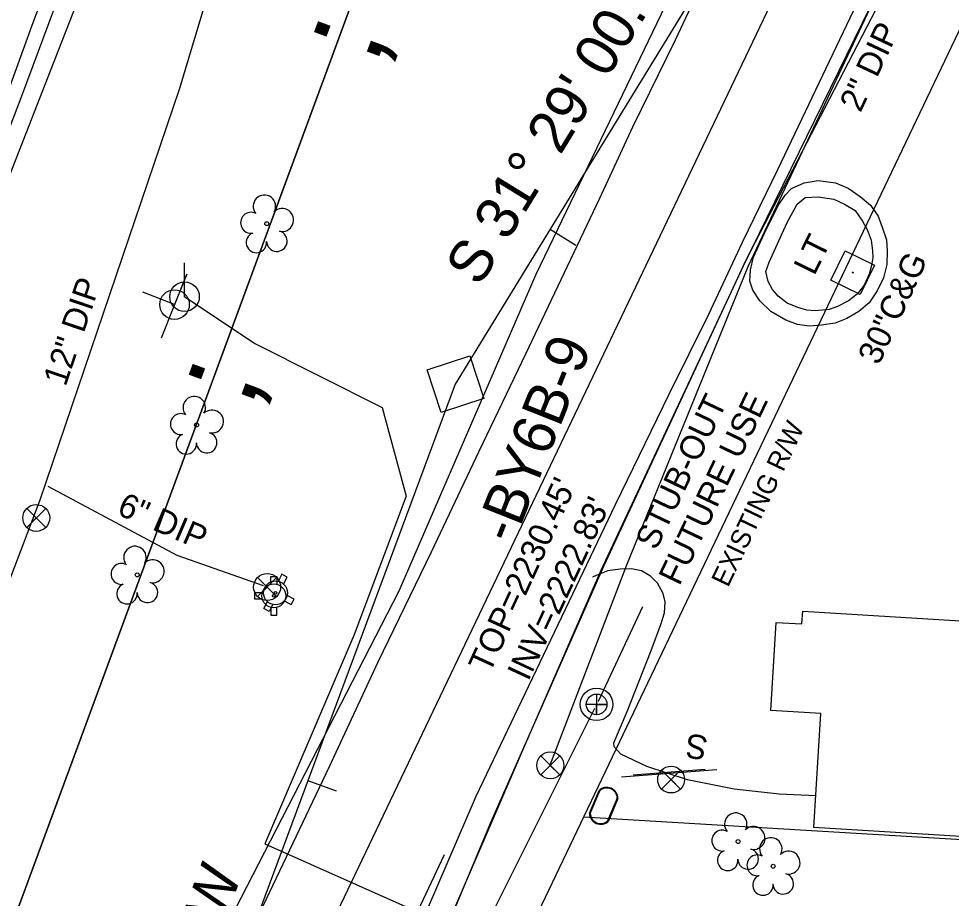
# Model space of a CAD drawing. Extents: x 945964 to 948456, y 631061 to 636061.
# Drawn here: x 947403.5 to 947557.8, y 634522.6 to 634668.2 of the extents above; entities that cross this region are included whole.
import ezdxf

# ---------------------------------------------------------------- set-up
doc = ezdxf.new("R2010")
doc.units = 0
for name, color, linetype in [('CTL Supplemental Horizontal and Vertical CELL', 7, 'Continuous'), ('Exist Building', 7, 'Continuous'), ('Exist Horizontal Alignment', 7, 'Continuous'), ('Exist Horizontal Baseline Alignment', 7, 'Continuous'), ('Exist Horizontal Baseline Alignment Direction Label', 7, 'Continuous'), ('Exist Horizontal Baseline Alignment Station Label', 7, 'Continuous'), ('Exist Horizontal Baseline Alignment Tick small', 7, 'Continuous'), ('Exist Other Culture Fence Line', 7, 'Continuous'), ('Exist Other Culture Sign CELL', 7, 'Continuous'), ('Exist Other Culture Sign Text', 7, 'Continuous'), ('Exist Property Line', 7, 'Continuous'), ('Exist Right of Way Control of Access CA Symbol CELL', 7, 'Continuous'), ('Exist Right of Way Control of Access Line', 7, 'Continuous'), ('Exist Right of Way Line', 7, 'Continuous'), ('Exist Right of Way Line Text', 7, 'Continuous'), ('Exist Roads Curbs', 7, 'Continuous'), ('Exist Roads Curbs Text', 7, 'Continuous'), ('Exist Roads EOP', 7, 'Continuous'), ('Exist Roads EOP Other', 7, 'Continuous'), ('Exist Utilities Gas UG Line SUE', 7, 'Continuous'), ('Exist Utilities Other Pole With Base CELL', 7, 'Continuous'), ('Exist Utilities Other Pole With Base Text', 7, 'Continuous'), ('Exist Utilities Power Joint Use Telephone CELL', 7, 'Continuous'), ('Exist Utilities Power Pole CELL', 7, 'Continuous'), ('Exist Utilities Sanitary Sewer Manhole CELL', 7, 'Continuous'), ('Exist Utilities Sanitary Sewer Manhole Text', 7, 'Continuous'), ('Exist Utilities Sanitary Sewer UG Line', 7, 'Continuous'), ('Exist Utilities Sanitary Sewer UG Line Invert Elevation', 7, 'Continuous'), ('Exist Utilities Telephone UG Cable SUE', 7, 'Continuous'), ('Exist Utilities Telephone UG FO SUE', 7, 'Continuous'), ('Exist Utilities TV UG Cable SUE', 7, 'Continuous'), ('Exist Utilities Water Fire Hydrant CELL', 7, 'Continuous'), ('Exist Utilities Water Meter CELL', 7, 'Continuous'), ('Exist Utilities Water UG Line SUE', 7, 'Continuous'), ('Exist Utilities Water UG Line SUE Text', 7, 'Continuous'), ('Exist Utilities Water Valve CELL', 7, 'Continuous'), ('Exist Vegetation Tree CELL', 7, 'Continuous')]:
    doc.layers.add(name, color=color, linetype=linetype)

# ---------------------------------------------------------------- blocks, each defined once
blk = doc.blocks.new('EXIST UTILITIES WATER FIRE HYDRANT')
at = {"layer": 'Exist Utilities Water Fire Hydrant CELL'}
blk.add_line((0, 0), (0, 0), dxfattribs=at)
for points in [[(-0.0103, 0.0382), (-0.0103, 0.064), (0.0103, 0.064), (0.0103, 0.0377)], [(-0.0382, 0.0103), (-0.064, 0.0103), (-0.064, -0.0103), (-0.0382, -0.0103)], [(-0.0103, -0.0382), (-0.0103, -0.064), (0.0103, -0.064), (0.0103, -0.0377)]]:
    blk.add_lwpolyline(points, dxfattribs=at)
for radius in [0.0395, 0.00485]:
    blk.add_circle((0, 0), radius, dxfattribs=at)
blk = doc.blocks.new('EXIST UTILITIES POWER JOINT USE TELEPHONE')
at = {"layer": 'Exist Utilities Power Joint Use Telephone CELL'}
blk.add_line((0, 0), (0, 0), dxfattribs=at)
blk.add_lwpolyline([(-0.1188, 0), (0.108, -0.0008), (0, -0.0004), (0, 0.1125)], dxfattribs=at)
blk.add_circle((0, 0.0001), 0.049, dxfattribs=at)
blk = doc.blocks.new('CTL SUPPLEMENTAL HORIZONTAL AND VERTICAL')
at = {"layer": 'CTL Supplemental Horizontal and Vertical CELL'}
blk.add_line((0, 0), (0, 0), dxfattribs=at)
blk.add_lwpolyline([(-0.0735, 0.074), (0.07475, 0.074), (0.07475, -0.0745), (-0.0735, -0.0745)], close=True, dxfattribs=at)
blk = doc.blocks.new('EXIST UTILITIES WATER METER')
at = {"layer": 'Exist Utilities Water Meter CELL'}
blk.add_line((0, 0), (0, 0), dxfattribs=at)
for points in [[(-0.0408, 0.034), (0.0408, 0.034)], [(-0.0408, 0.0312), (0.0408, 0.0312)], [(0.0408, -0.0312), (-0.0413, -0.0312)], [(0.0408, -0.034), (-0.0413, -0.034)]]:
    blk.add_lwpolyline(points, dxfattribs=at)
for centre, radius, start, end in [((-0.0261, -0.0001), 0.0371, 113.178, 245.9794), ((-0.0259, -0.0001), 0.0347, 115.3009, 243.7824), ((0.0259, 0), 0.0371, 293.6483, 66.3084), ((0.0261, 0), 0.0345, 295.1272, 64.8728)]:
    blk.add_arc(centre, radius, start, end, dxfattribs=at)
blk = doc.blocks.new('EXIST UTILITIES WATER VALVE')
at = {"layer": 'Exist Utilities Water Valve CELL'}
blk.add_lwpolyline([(0.0315, 0.0315), (-0.0315, -0.0315), (0, 0), (0.0315, -0.0315), (-0.0315, 0.0315)], dxfattribs=at)
blk.add_circle((0, 0), 0.0445, dxfattribs=at)

msp = doc.modelspace()

# ---------------------------------------------------------------- linework, layer by layer
at = {"layer": 'Exist Building'}
msp.add_lwpolyline([(947533.24, 634570.16), (947642.08, 634563.46), (947645.55, 634619.91), (947640.35, 634620.23), (947641.33, 634636.15), (947646.37, 634635.84), (947646.93, 634644.89), (947682.78, 634642.68), (947675.59, 634525.72), (947535.1, 634534.36), (947536.26, 634553.22), (947527.95, 634553.73), (947528.84, 634568.29), (947533.11, 634568.02)], close=True, dxfattribs=at)
at = {"layer": 'Exist Horizontal Alignment'}
msp.add_line((947634.91, 634894.66), (947405.56, 634414.27), dxfattribs=at)
at = {"layer": 'Exist Horizontal Baseline Alignment'}
for p, q in [((947700.35, 634974.44), (947475.75, 634607.69)), ((947475.75, 634607.69), (947365.74, 634311.71))]:
    msp.add_line(p, q, dxfattribs=at)
at = {"layer": 'Exist Horizontal Baseline Alignment Tick small'}
for p, q in [((947491.45, 634633.33), (947495.71, 634630.72)), ((947451.38, 634542.13), (947456.07, 634540.39))]:
    msp.add_line(p, q, dxfattribs=at)
at = {"layer": 'Exist Other Culture Fence Line'}
msp.add_lwpolyline([(947583.12, 635010.41), (947482.79, 634736.39), (947398.27, 634507.1), (947363.07, 634405.71)], dxfattribs=at)
at = {"layer": 'Exist Other Culture Sign CELL'}
for p, q in [((947519.04, 634543.87), (947503.27, 634542.67)), ((947505.17, 634543.08), (947517.12, 634544.02))]:
    msp.add_line(p, q, dxfattribs=at)
at = {"layer": 'Exist Property Line'}
msp.add_lwpolyline([(947694.12, 634524.25), (947693.06, 634524.31), (947496.95, 634536.07)], dxfattribs=at)
at = {"layer": 'Exist Right of Way Control of Access CA Symbol CELL'}
msp.add_line((947437.37, 634613.19), (947437.37, 634613.19), dxfattribs=at)
at = {"layer": 'Exist Right of Way Control of Access Line'}
msp.add_lwpolyline([(947398.27, 634507.1), (947482.79, 634736.39)], dxfattribs=at)
at = {"layer": 'Exist Right of Way Line'}
msp.add_line((947661.98, 634881.73), (947432.63, 634401.34), dxfattribs=at)
at = {"layer": 'Exist Roads Curbs'}
for points in [[(947414.14, 634682.65), (947403.95, 634655.19), (947386.91, 634610.72)], [(947544.59, 634631.52), (947544.76, 634629.77), (947544.84, 634628.67), (947544.61, 634627.36), (947544.23, 634625.89), (947543.4, 634624.1), (947542.26, 634622.62), (947540.82, 634621.49), (947538.97, 634620.54), (947537.59, 634620.05), (947535.29, 634619.82), (947533.9, 634619.97), (947532.45, 634620.38), (947530.64, 634621.13), (947529.19, 634622.27), (947528.24, 634623.36), (947527.5, 634624.68), (947527.16, 634626.34), (947527.68, 634627.89), (947530.69, 634634.44), (947532.32, 634637.52), (947533.65, 634638.58), (947535.82, 634638.68), (947538.39, 634638.33), (947540.15, 634637.49), (947541.91, 634636.43), (947543.14, 634634.66), (947543.91, 634633.29), (947544.59, 634631.52)]]:
    msp.add_lwpolyline(points, dxfattribs=at)
at = {"layer": 'Exist Roads EOP'}
for points in [[(947416.94, 634696.72), (947405.89, 634667.48), (947397.84, 634645.46)], [(947398.51, 634422.19), (947405.3, 634438.3), (947412.75, 634454.81), (947421.56, 634473.6), (947428.38, 634488.03), (947437.98, 634508.75), (947454.98, 634544.45), (947463.03, 634561.75), (947471.85, 634579.95), (947479.72, 634596.64), (947487.41, 634612.7), (947499.7, 634638.47), (947505.16, 634650.3), (947512.22, 634664.7), (947520.77, 634683.05)], [(947469.78, 634517.62), (947479.2, 634539.5), (947486.18, 634554.11), (947494.6, 634571.73), (947502.28, 634587.82), (947502.28, 634587.82), (947511.16, 634606.03), (947511.16, 634606.03), (947517.72, 634619.27), (947517.72, 634619.27), (947523.3, 634631.23), (947529.13, 634643.22), (947542.23, 634670.73)], [(947409.98, 634383.21), (947412.91, 634391.97), (947419.73, 634410.82), (947424.3, 634422.36), (947430.21, 634435.76), (947435.78, 634448.39), (947442.34, 634461.96), (947446.32, 634471.45), (947464.44, 634509.58), (947473.96, 634529.87)]]:
    msp.add_lwpolyline(points, dxfattribs=at)
at = {"layer": 'Exist Roads EOP Other'}
for points in [[(947527.21, 634633.28), (947529.29, 634637.44), (947530.32, 634639.01), (947531.4, 634640.11), (947533.47, 634641.05), (947535.81, 634641.39), (947538.65, 634641.04), (947540.77, 634640.16), (947542.75, 634638.78), (947544.48, 634637.34), (947545.73, 634635.49), (947546.38, 634633.71), (947547.1, 634631.6), (947547.23, 634629.73), (947547.15, 634627.5), (947546.58, 634625.33), (947545.53, 634623.16), (947544.21, 634621.18), (947542.52, 634619.71), (947540.52, 634618.56), (947538.61, 634617.79), (947536.35, 634617.46), (947534.29, 634617.33), (947532.4, 634617.6), (947530.43, 634618.27), (947527.97, 634619.73), (947526.13, 634621.51), (947525, 634623.26), (947524.51, 634624.75), (947524.6, 634626.63), (947525.09, 634628.71), (947527.21, 634633.28)], [(947535.42, 634539.57), (947529.33, 634539.85), (947521.92, 634540.69), (947514.17, 634542.23), (947507.43, 634544.45), (947503.13, 634546.5), (947502.07, 634547.67), (947502.01, 634548.33), (947504.22, 634553.54), (947508.15, 634563.64), (947509.77, 634567.94), (947510.39, 634569.89), (947510.5, 634571.67), (947510.14, 634573.07), (947509.22, 634574.8), (947508.04, 634575.92), (947506.59, 634576.79), (947504.91, 634577.16), (947503.03, 634577.11), (947501, 634576.82), (947499.08, 634576.03), (947498.46, 634575.78)]]:
    msp.add_lwpolyline(points, dxfattribs=at)
at = {"layer": 'Exist Utilities Gas UG Line SUE'}
msp.add_lwpolyline([(947411.39, 634357.39), (947432.81, 634416.73), (947448.6, 634452.89), (947466.55, 634499.81), (947487.41, 634548.32), (947499.89, 634576.91), (947523.42, 634627.31), (947572, 634726.59), (947594.13, 634772.03), (947617.16, 634817.01), (947638.9, 634858.44), (947663.24, 634905.68), (947679.1, 634930.67), (947690.74, 634971.53), (947694.38, 634980.36)], dxfattribs=at)
at = {"layer": 'Exist Utilities Other Pole With Base CELL'}
msp.add_line((947541.51, 634626.19), (947541.51, 634626.19), dxfattribs=at)
msp.add_lwpolyline([(947537.89, 634624.91), (947540.24, 634629.77), (947545.1, 634627.42), (947542.75, 634622.56), (947537.89, 634624.91)], dxfattribs=at)
msp.add_circle((947541.51, 634626.19), 0.0707, dxfattribs=at)
at = {"layer": 'Exist Utilities Power Pole CELL'}
for q in [(947430.97, 634627.8), (947430.97, 634622.18)]:
    msp.add_line((947430.97, 634622.18), q, dxfattribs=at)
msp.add_circle((947430.97, 634622.18), 2.45, dxfattribs=at)
at = {"layer": 'Exist Utilities Sanitary Sewer Manhole CELL'}
msp.add_lwpolyline([(947499.14, 634556.43), (947499.14, 634553.01), (947499.14, 634554.72), (947500.86, 634554.72), (947497.43, 634554.72)], dxfattribs=at)
for radius in [2.69, 1.71]:
    msp.add_circle((947499.14, 634554.72), radius, dxfattribs=at)
at = {"layer": 'Exist Utilities Sanitary Sewer UG Line'}
for p, q in [((947499.45, 634555.25), (947506.79, 634570.92)), ((947498.81, 634554.04), (947440.58, 634437.82))]:
    msp.add_line(p, q, dxfattribs=at)
at = {"layer": 'Exist Utilities Telephone UG Cable SUE'}
for points in [[(947413.87, 634369.61), (947433.57, 634416.72), (947442.44, 634436.17), (947447.24, 634453.55), (947466.46, 634498.8), (947481.78, 634535.47), (947500.33, 634577.57), (947523.94, 634628.41), (947556.15, 634690.55), (947585.48, 634752.36), (947618.07, 634816.9), (947652.13, 634887.42), (947667.25, 634909.79), (947678.29, 634930.7), (947702.66, 634974.26), (947761.95, 634955.83)], [(947430.95, 634622.2), (947442.59, 634614.44), (947463.67, 634603.83), (947467.62, 634589.16), (947458.97, 634566.13), (947444.28, 634531.63), (947481.51, 634515.03), (947544.79, 634509.47)]]:
    msp.add_lwpolyline(points, dxfattribs=at)
at = {"layer": 'Exist Utilities Telephone UG FO SUE'}
msp.add_lwpolyline([(947308.67, 634385.7), (947324.73, 634436.61), (947349.98, 634503.81), (947399.79, 634636.69), (947424.5, 634699.87), (947441.41, 634747.2), (947458.37, 634791.14), (947474.8, 634833.81), (947506.49, 634914.69), (947536.7, 634997.68), (947556.25, 635036.97), (947600.82, 635144.03), (947621.01, 635192.27), (947646.68, 635247.96)], dxfattribs=at)
at = {"layer": 'Exist Utilities TV UG Cable SUE'}
msp.add_lwpolyline([(947382.54, 634389.92), (947399.72, 634437.38), (947435.56, 634513.4), (947466.49, 634573.53), (947489.17, 634625.92), (947525.67, 634701.8), (947534.64, 634716.36), (947565, 634704.98), (947562.08, 634710.59), (947568.98, 634716.83), (947594.56, 634769.03), (947615.55, 634818.19), (947635.03, 634859.7), (947660.61, 634907.24), (947669.39, 634919.51), (947686.1, 634927.4), (947706.25, 634931.09), (947740.09, 634929.49), (947766.68, 634921.63)], dxfattribs=at)
at = {"layer": 'Exist Utilities Water Fire Hydrant CELL'}
msp.add_line((947445.75, 634572.68), (947445.75, 634572.68), dxfattribs=at)
for points in [[(947445.24, 634574.59), (947445.24, 634575.88), (947446.26, 634575.88), (947446.26, 634574.57)], [(947443.84, 634573.19), (947442.55, 634573.19), (947442.55, 634572.17), (947443.84, 634572.17)], [(947445.24, 634570.77), (947445.24, 634569.48), (947446.26, 634569.48), (947446.26, 634570.79)]]:
    msp.add_lwpolyline(points, dxfattribs=at)
for radius in [1.98, 0.243]:
    msp.add_circle((947445.75, 634572.68), radius, dxfattribs=at)
at = {"layer": 'Exist Utilities Water UG Line SUE'}
for points in [[(947333.3, 634361.13), (947344.16, 634401.76), (947357.81, 634451.14), (947384.44, 634529.02), (947407.08, 634588.54), (947430.15, 634656.55), (947446.25, 634710.16), (947454.42, 634734.75), (947483.65, 634818.88), (947488.49, 634852.55), (947495.18, 634873.34), (947521.89, 634942.67), (947539.14, 634983.73), (947561.83, 635038.36), (947610.1, 635133.58), (947618.08, 635162.67), (947624.92, 635188.11), (947640.46, 635224.79)], [(947491.41, 634544.56), (947504.16, 634577.8), (947524.19, 634627.18), (947571.25, 634726.87), (947593.54, 634772.54), (947616.5, 634817.63), (947637.6, 634859.81), (947654.81, 634893.42), (947676.77, 634924.49), (947688.68, 634929.15), (947706.47, 634932.11)], [(947444.06, 634574.33), (947429.78, 634579.37), (947408.39, 634590.78)]]:
    msp.add_lwpolyline(points, dxfattribs=at)
at = {"layer": 'Exist Utilities Water Valve CELL'}
for points in [[(947408.02, 634587.15), (947404.87, 634584), (947406.44, 634585.58), (947408.02, 634584), (947404.87, 634587.15)], [(947446.21, 634575.71), (947443.06, 634572.56), (947444.64, 634574.13), (947446.21, 634572.56), (947443.06, 634575.71)], [(947493.06, 634546.19), (947489.91, 634543.04), (947491.48, 634544.62), (947493.06, 634543.04), (947489.91, 634546.19)]]:
    msp.add_lwpolyline(points, dxfattribs=at)
for centre in [(947406.44, 634585.58), (947444.64, 634574.13), (947491.48, 634544.62)]:
    msp.add_circle(centre, 2.23, dxfattribs=at)
at = {"layer": 'Exist Vegetation Tree CELL'}
for p, q in [((947444.58, 634634.27), (947444.58, 634634.27)), ((947432.96, 634600.94), (947432.96, 634600.94)), ((947423.15, 634576.15), (947423.15, 634576.15)), ((947522.55, 634532.02), (947522.55, 634532.02)), ((947528.35, 634527.93), (947528.35, 634527.93))]:
    msp.add_line(p, q, dxfattribs=at)
for centre in [(947444.58, 634634.27), (947432.96, 634600.94), (947423.15, 634576.15), (947522.55, 634532.02), (947528.35, 634527.93)]:
    msp.add_circle(centre, 0.326, dxfattribs=at)
for centre, radius, start, end in [((947444.19, 634637.14), 1.86, 330.1651, 219.7134), ((947441.97, 634634.42), 1.73, 62.6636, 279.3457), ((947447.12, 634634.86), 1.9, 257.1011, 134.1999), ((947442.87, 634631.15), 1.69, 111.5671, 6.231), ((947446.25, 634631.37), 1.7, 181.2822, 74.56), ((947432.58, 634603.82), 1.86, 330.1651, 219.7134), ((947435.51, 634601.53), 1.9, 257.1011, 134.1999), ((947430.36, 634601.1), 1.73, 62.6636, 279.3457), ((947431.26, 634597.82), 1.69, 111.5671, 6.231), ((947434.64, 634598.04), 1.7, 181.2822, 74.56), ((947422.77, 634579.02), 1.86, 330.1651, 219.7134), ((947425.7, 634576.73), 1.9, 257.1011, 134.1999), ((947420.55, 634576.3), 1.73, 62.6636, 279.3457), ((947421.45, 634573.02), 1.69, 111.5671, 6.231), ((947424.83, 634573.25), 1.7, 181.2822, 74.56), ((947522.16, 634534.89), 1.86, 330.1651, 219.7134), ((947519.94, 634532.17), 1.73, 62.6636, 279.3457), ((947525.1, 634532.6), 1.9, 257.1011, 134.1999), ((947527.96, 634530.8), 1.86, 330.1651, 219.7134), ((947524.22, 634529.12), 1.7, 181.2822, 74.56), ((947520.84, 634528.9), 1.69, 111.5671, 6.231), ((947525.74, 634528.08), 1.73, 62.6636, 279.3457), ((947530.9, 634528.52), 1.9, 257.1011, 134.1999), ((947526.65, 634524.81), 1.69, 111.5671, 6.231), ((947530.02, 634525.03), 1.7, 181.2822, 74.56)]:
    msp.add_arc(centre, radius, start, end, dxfattribs=at)

# ---------------------------------------------------------------- block references
at = {"layer": 'CTL Supplemental Horizontal and Vertical CELL', "xscale": 50, "yscale": 50, "rotation": 18.132156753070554}
msp.add_blockref('CTL SUPPLEMENTAL HORIZONTAL AND VERTICAL', (947475.75, 634607.69), dxfattribs=at)
at = {"layer": 'Exist Utilities Power Joint Use Telephone CELL', "xscale": 50.000000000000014, "yscale": 50.000000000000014, "rotation": 68.44419752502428}
msp.add_blockref('EXIST UTILITIES POWER JOINT USE TELEPHONE', (947429.32, 634620.88), dxfattribs=at)
at = {"layer": 'Exist Utilities Water Fire Hydrant CELL', "xscale": 50.00000000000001, "yscale": 49.99999999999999, "rotation": 152.23700562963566}
msp.add_blockref('EXIST UTILITIES WATER FIRE HYDRANT', (947446.02, 634573.17), dxfattribs=at)
at = {"layer": 'Exist Utilities Water Meter CELL', "xscale": 50, "yscale": 50.00000000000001, "rotation": 67.18004480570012}
msp.add_blockref('EXIST UTILITIES WATER METER', (947500.32, 634537.93), dxfattribs=at)
at = {"layer": 'Exist Utilities Water Valve CELL', "xscale": 50, "yscale": 50}
msp.add_blockref('EXIST UTILITIES WATER VALVE', (947511.47, 634542.28), dxfattribs=at)

# ---------------------------------------------------------------- texts
at = {"layer": 'Exist Horizontal Baseline Alignment Direction Label'}
for s, rotation, p in [('S 31%%d 29\' 00.5" W', 58.5165, (947479.76, 634623.65)), ('S 20%%d 23\' 19.9" W', 69.6112, (947414.95, 634457.75))]:
    msp.add_text(s, height=7, rotation=rotation, dxfattribs=at).set_placement(p)
at = {"layer": 'Exist Horizontal Baseline Alignment Station Label'}
msp.add_text('-BY6B-9', height=7, rotation=68.3391, dxfattribs=at).set_placement((947485.34, 634581.05))
at = {"layer": 'Exist Other Culture Sign Text'}
msp.add_text('S', height=4, rotation=171.0819, dxfattribs=at).set_placement((947517.75, 634549.38))
at = {"layer": 'Exist Right of Way Control of Access CA Symbol CELL'}
for p in [(947462.56, 634660.25), (947441.82, 634603.55)]:
    msp.add_text(';', height=15, rotation=69.764, dxfattribs=at).set_placement(p)
at = {"layer": 'Exist Right of Way Line Text'}
msp.add_text('EXISTING R/W', height=3.2, rotation=64.4793, dxfattribs=at).set_placement((947520.88, 634573.95))
at = {"layer": 'Exist Roads Curbs Text'}
msp.add_text('30"C&G', height=4, rotation=65.2682, dxfattribs=at).set_placement((947545.84, 634610.7))
at = {"layer": 'Exist Utilities Other Pole With Base Text'}
msp.add_text('LT', height=4, rotation=63.7672, dxfattribs=at).set_placement((947535.16, 634625.52))
at = {"layer": 'Exist Utilities Sanitary Sewer Manhole Text'}
msp.add_text("TOP=2230.45'", height=4, rotation=65.2626, dxfattribs=at).set_placement((947481.44, 634559.68))
at = {"layer": 'Exist Utilities Sanitary Sewer UG Line Invert Elevation'}
for s, rotation, p in [('STUB-OUT', 64.4419, (947509, 634580.06)), ('FUTURE USE', 64.4419, (947512.84, 634574.19)), ("INV=2222.83'", 65.0589, (947487.84, 634558.42))]:
    msp.add_text(s, height=4, rotation=rotation, dxfattribs=at).set_placement(p)
at = {"layer": 'Exist Utilities Water UG Line SUE Text'}
for s, rotation, p in [('2" DIP', 64.7288, (947542.79, 634652.52)), ('12" DIP', 71.2625, (947411.29, 634607.19)), ('6" DIP', 336.6479, (947419.61, 634586.23))]:
    msp.add_text(s, height=4, rotation=rotation, dxfattribs=at).set_placement(p)

doc.saveas('drawing.dxf')
